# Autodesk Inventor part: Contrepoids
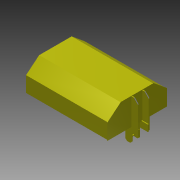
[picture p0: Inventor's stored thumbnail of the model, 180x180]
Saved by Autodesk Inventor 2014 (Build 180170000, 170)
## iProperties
Created: 2015-07
Part Number: Contrepoids
Material: Générique
Document SubType Name: Modeling
Designer: OL
Density: 1 g/cm^3
Appearance: Par défaut
Author: OL
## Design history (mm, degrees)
sketch "Esquisse1"
  geometry: L1 (-358, 0)-(358, 0); L2 (358, 0)-(358, 185); L3 (199, 316)-(-199, 316); L4 (-358, 185)-(-358, 0); L5 (-358, 185)-(-199, 316); L6 (199, 316)-(358, 185); L7 (-199.897, 318.5)-(199.897, 318.5); L8 (199.897, 318.5)-(360.5, 186.179); L9 (360.5, 186.179)-(360.5, -2.5); L10 (360.5, -2.5)-(-360.5, -2.5); L11 (-360.5, -2.5)-(-360.5, 186.179); L12 (-360.5, 186.179)-(-199.897, 318.5); 1 further point
  constraints: 24 end point, 4 parallel, 2 perpendicular, 1 horizontal, 5 other
  dimensions: "d0" = 358 distance from line of L4 point (0, 0) (= 0.5 x d1); "d1" = 716 distance between parallel lines of L2 L4; "d2" = 316 distance between parallel lines of L3 L1; "d3" = 131 vertical distance of L3.start L2.end; "d4" = 159 horizontal distance of L3.start L2.end; "d5" = 159 horizontal distance of L4.start L3.end; "d6" = 131 vertical distance of L4.start L3.end; "d7" = 0 distance from line of point (0, 0) L1; "d20" = 2.5 distance between parallel lines of L3 L7
extrude "Extrusion1" new body sketch "Esquisse1" distance "d9" = 1000; taper "d10" = 0 deg
sketch "Esquisse4"
  geometry: L1 (-318.5, 199.897)-(-318.5, -199.897) reference; L2 (-318.5, -199.897)-(-186.179, -360.5) reference; L3 (-186.179, -360.5)-(2.5, -360.5) reference; L4 (2.5, -360.5)-(2.5, 360.5) reference; L5 (2.5, 360.5)-(-186.179, 360.5) reference; L6 (-186.179, 360.5)-(-318.5, 199.897) reference; L7 (-188.538, 365.5)-(7.5, 365.5); L8 (7.5, 365.5)-(7.5, -365.5); L9 (7.5, -365.5)-(-188.538, -365.5); L10 (-188.538, -365.5)-(-323.5, -201.692); L11 (-323.5, -201.692)-(-323.5, 201.692); L12 (-323.5, 201.692)-(-188.538, 365.5); 1 further point
  constraints: 12 end point, 5 other
  dimensions: "d21" = 5 distance between parallel lines of L5 L7
extrude "Extrusion3" join sketch "Esquisse4" distance "d22" = 5; taper "d23" = 0 deg
sketch "Esquisse5"
  geometry: L1 (7.5, 365.5)-(-188.538, 365.5) reference; L2 (-188.538, -365.5)-(7.5, -365.5) reference; L3 (71.5, 61)-(-318.5, 61); L4 (-318.5, 61)-(-318.5, 71); L5 (-318.5, 71)-(71.5, 71); L6 (71.5, 71)-(71.5, 61); L7 (71.5, -71)-(-318.5, -71); L8 (-318.5, -71)-(-318.5, -61); L9 (-318.5, -61)-(71.5, -61); L10 (71.5, -61)-(71.5, -71); L11 (-323.5, 201.692)-(-323.5, -201.692) reference; 1 further point
  constraints: 16 end point, 4 parallel, 2 horizontal, 2 perpendicular
  dimensions: "d26" = 390 distance of L7.start L7.end; "d27" = 390 distance of L3.start L3.end; "d28" = 10 distance between parallel lines of L7 L9; "d29" = 10 distance between parallel lines of L5 L3; "d30" = 122 distance between parallel lines of L3 L9; "d31" = 294.5 distance between parallel lines of L2 L7; "d32" = 294.5 distance between parallel lines of L1 L5 (derived); "d35" = 5 distance between parallel lines of L11 L4; "d36" = 5 distance between parallel lines of L11 L8
extrude "Extrusion4" join sketch "Esquisse5" distance "d33" = 80; taper "d34" = 0 deg
sketch "Esquisse6"
  geometry: L1 (80, 390)-(80, 0) reference; L2 (0, 390)-(80, 390) reference; L3 (30, 390)-(80, 340); 1 further point
  constraints: 2 end point, 2 point on line
  dimensions: "d37" = 50 horizontal distance of L3.start L3.end; "d38" = 50 horizontal distance of L3.start L3.end
extrude "Extrusion5" cut sketch "Esquisse6" stored distance "d39" = 80; taper "d40" = 0 deg
sketch "Esquisse7"
  geometry: L1 (71.5, -61)-(-268.5, -61) reference; L2 (-268.5, 61)-(71.5, 61) reference; L3 (7.5, -61)-(7.5, 61) reference; L4 (2.5, -61)-(82.5, -61); L5 (82.5, -61)-(82.5, -51); L6 (82.5, -51)-(2.5, -51); L7 (2.5, -51)-(2.5, -61); L8 (2.5, 61)-(82.5, 61); L9 (82.5, 61)-(82.5, 51); L10 (82.5, 51)-(2.5, 51); L11 (2.5, 51)-(2.5, 61); L12 (7.5, 71)-(7.5, 365.5) reference; 1 further point
  constraints: 16 end point, 4 parallel, 2 horizontal, 2 perpendicular, 2 point on line
  dimensions: "d41" = 80 distance of L9.end L10.end; "d43" = 5 distance between parallel lines of L12 L11; "d44" = 5 distance between parallel lines of L3 L7; "d45" = 80 distance of L5.end L6.end; "d46" = 10 distance of L4.end L5.end; "d47" = 10 distance of L8.end L9.end
extrude "Extrusion6" join sketch "Esquisse7" distance "d48" = 1320; taper "d49" = 0 deg
sketch "Esquisse8"
  geometry: L1 (-1085, 80)-(-85, 80) reference; L2 (0, 80)-(0, 0) reference; L3 (-175, 70)-(-95, 70); L4 (-95, 70)-(-95, -100); L5 (-115, -120)-(-155, -120); L6 (-175, -100)-(-175, 70); L7 (-155, -120)-(-175, -100); L8 (-115, -120)-(-95, -100); 1 further point
  constraints: 12 end point, 2 parallel, 1 horizontal, 1 perpendicular
  dimensions: "d50" = 95 distance between parallel lines of L4 L2; "d51" = 80 distance of L3.start L3.end; "d53" = 190 distance between parallel lines of L5 L3; "d54" = 20 horizontal distance of L5.end L6.start; "d55" = 20 horizontal distance of L5.end L6.start; "d56" = 20 horizontal distance of L5.start L4.end; "d57" = 20 horizontal distance of L5.start L4.end; "d58" = 10 distance between parallel lines of L1 L3
extrude "Extrusion7" join sketch "Esquisse8" distance "d59" = 10; taper "d60" = 0 deg
mirror "Symétrie1"
sketch "Esquisse9"
  geometry: L1 (-95, 70)-(-175, 70) reference; L2 (-175, 70)-(-175, -100) reference; L3 (-95, -100)-(-95, 70) reference; L4 (-175, -50)-(-95, -50); L5 (-95, -50)-(-95, -40); L6 (-95, -40)-(-175, -40); L7 (-175, -40)-(-175, -50); 1 further point
  constraints: 8 end point, 2 parallel, 2 point on line, 1 horizontal, 1 perpendicular
  dimensions: "d61" = 10 distance between parallel lines of L4 L6; "d63" = 110 distance between parallel lines of L6 L1
extrude "Extrusion8" join sketch "Esquisse9" stored distance "d64" = 10; taper "d65" = 0 deg
sketch "Esquisse10"
  geometry: L1 (1320, 0)-(0, 0) reference; L2 (0, 0)-(80, 0); L3 (80, 0)-(80, -100); L4 (60, -120)-(20, -120); L5 (0, -100)-(0, 0); L6 (0, -100)-(20, -120); L7 (60, -120)-(80, -100); C1 r 10 at (40, -90); 1 further point
  constraints: 12 end point, 2 parallel, 1 centre point, 1 horizontal, 1 perpendicular
  dimensions: "d66" = 120 distance between parallel lines of L4 L1; "d67" = 20 horizontal distance of L5.start L4.end; "d68" = 20 horizontal distance of L4.start L3.end; "d69" = 20 horizontal distance of L4.start L3.end; "d70" = 20 horizontal distance of L5.start L4.end; "d71" = 80 distance between parallel lines of L5 L3; "d72" = 20 diameter of C1; "d73" = 90 distance from line of L2 C1.centre; "d74" = 40 distance from line of L3 C1.centre
extrude "Extrusion9" join sketch "Esquisse10" distance "d75" = 10; taper "d76" = 0 deg
mirror "Symétrie2"
sketch "Esquisse11"
  geometry: L1 (0, 0)-(-235, 0) reference; L2 (-235, 0)-(-235, -180) reference; C1 r 10 at (-225, -10); 1 further point
  constraints: 1 centre point, 1 tangent
  dimensions: "d77" = 20 diameter of C1; "d80" = 10 distance from line of L1 C1.centre (derived); "d81" = 10 distance from line of L2 C1.centre
extrude "Extrusion10" join sketch "Esquisse11" stored distance "d82" = 10; taper "d83" = 0 deg
node "Solide1"
